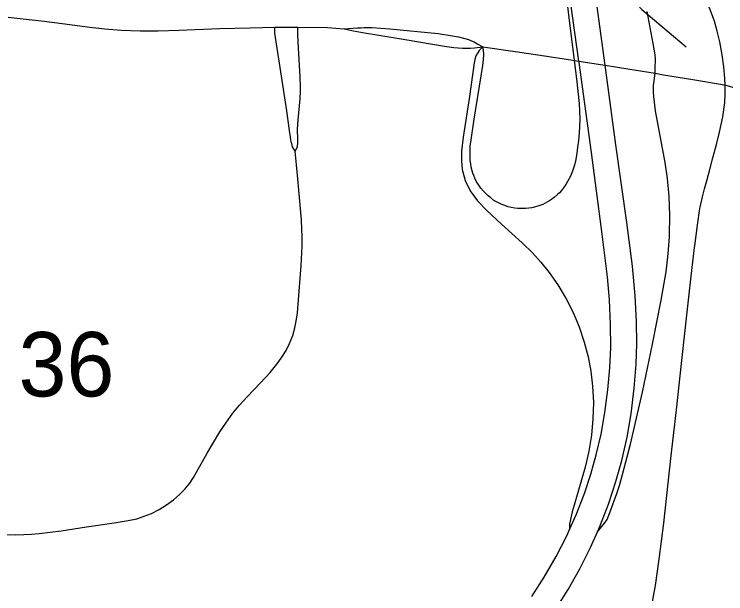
# Model space of a CAD drawing. Extents: x 0 to 34, y 0 to 22.
# Drawn here: x 24.2695 to 24.7319, y 15.2254 to 15.6018 of the extents above; entities that cross this region are included whole.
import ezdxf

# ---------------------------------------------------------------- set-up
doc = ezdxf.new("R2010")
doc.units = 0
for name, color, linetype in [('GM_X_City_Street', 7, 'Continuous'), ('GM_X_County_Road', 7, 'Continuous'), ('GM_X_Interchange_Ramps', 7, 'Continuous'), ('GM_X_Minor_River', 7, 'Continuous'), ('GM_X_Section_Text', 7, 'Continuous'), ('GM_X_State_Route', 7, 'Continuous'), ('GM_X_Township_Road', 7, 'Continuous')]:
    doc.layers.add(name, color=color, linetype=linetype)

msp = doc.modelspace()

# ---------------------------------------------------------------- linework, layer by layer
at = {"layer": 'GM_X_City_Street'}
msp.add_line((24.48399, 15.59231), (24.48502, 15.59207), dxfattribs=at)
for points in [[(24.26558, 15.59991), (24.28906, 15.59739), (24.30078, 15.59585), (24.31862, 15.59332), (24.32847, 15.59223), (24.33897, 15.59149), (24.35136, 15.591), (24.36313, 15.59096), (24.37676, 15.59139), (24.40285, 15.59256), (24.42276, 15.59298), (24.43881, 15.59337), (24.45375, 15.59335), (24.47322, 15.5932), (24.48399, 15.59231)], [(24.45214, 15.51274), (24.45106, 15.51453), (24.45047, 15.51575), (24.44984, 15.51772), (24.44961, 15.51864), (24.44929, 15.52032), (24.4482, 15.52785), (24.44665, 15.53915), (24.44197, 15.56998), (24.43928, 15.58662), (24.43893, 15.58951), (24.43879, 15.5911), (24.43881, 15.59337)], [(24.45214, 15.51274), (24.45286, 15.51385), (24.45327, 15.51481), (24.45354, 15.51584), (24.45365, 15.51659), (24.45373, 15.51751), (24.45379, 15.51868), (24.45378, 15.52066), (24.4537, 15.52696), (24.45399, 15.53323), (24.45535, 15.54681), (24.4555, 15.55176), (24.45549, 15.55424), (24.45531, 15.56103), (24.45428, 15.57967), (24.45392, 15.58867), (24.45375, 15.59335)], [(24.48399, 15.59231), (24.49257, 15.59302), (24.49495, 15.59305), (24.49702, 15.59315), (24.50187, 15.59318), (24.51373, 15.59235), (24.54503, 15.5892), (24.55299, 15.58803), (24.5583, 15.587), (24.56471, 15.58528), (24.56664, 15.58461), (24.5684, 15.5838), (24.57091, 15.58238), (24.57415, 15.58053)], [(24.48502, 15.59207), (24.49012, 15.5909), (24.49706, 15.58964), (24.50518, 15.58832), (24.52364, 15.58548), (24.54146, 15.58239), (24.5491, 15.58102), (24.55512, 15.58025), (24.56088, 15.57983), (24.56414, 15.57971), (24.56607, 15.57977), (24.56866, 15.58006), (24.57415, 15.58053)], [(24.57415, 15.58053), (24.5982, 15.57713), (24.6141, 15.5747), (24.63129, 15.57209), (24.6334, 15.57177), (24.63655, 15.57128), (24.65207, 15.56886), (24.65354, 15.56864), (24.66968, 15.56617), (24.68598, 15.56345), (24.69153, 15.56253), (24.7106, 15.55939)], [(24.26461, 15.26383), (24.27024, 15.26365), (24.27585, 15.26378), (24.28084, 15.26402), (24.28581, 15.26444), (24.30001, 15.26627), (24.31659, 15.2688), (24.33441, 15.27136), (24.34366, 15.27286), (24.34917, 15.27414), (24.35397, 15.27566), (24.35865, 15.27753), (24.36372, 15.28009), (24.36854, 15.28306), (24.3731, 15.28643), (24.3769, 15.28975), (24.38041, 15.29338), (24.38361, 15.29729), (24.38608, 15.30095), (24.395, 15.31663), (24.40324, 15.33044), (24.40696, 15.33611), (24.41169, 15.34257), (24.41599, 15.34781), (24.42091, 15.35335), (24.42953, 15.36229), (24.43584, 15.36919), (24.44101, 15.37547), (24.44389, 15.37959), (24.44615, 15.38338), (24.4484, 15.3879), (24.45049, 15.39318), (24.45193, 15.39801), (24.45283, 15.40233), (24.45358, 15.40793), (24.45495, 15.42467), (24.45592, 15.43831), (24.45658, 15.45137), (24.45657, 15.45795), (24.45649, 15.46176), (24.45618, 15.46844), (24.45588, 15.47302), (24.45363, 15.49731), (24.45214, 15.51274)]]:
    msp.add_lwpolyline(points, dxfattribs=at)
at = {"layer": 'GM_X_County_Road'}
for points in [[(24.72966, 15.57549), (24.72811, 15.58377), (24.72646, 15.59087), (24.72458, 15.59729), (24.72168, 15.60533), (24.71787, 15.61436), (24.71311, 15.62574), (24.71086, 15.63191), (24.7086, 15.63779), (24.70674, 15.64386), (24.70469, 15.65101), (24.70253, 15.66042), (24.70167, 15.66422)], [(24.7316, 15.55576), (24.73126, 15.5602), (24.73077, 15.56755), (24.72966, 15.57549)], [(24.71517, 15.47555), (24.71531, 15.47652), (24.71688, 15.48309), (24.71815, 15.48828), (24.71982, 15.49445), (24.72158, 15.50092), (24.72363, 15.50855), (24.72599, 15.51708), (24.72784, 15.52511), (24.7301, 15.5352), (24.73127, 15.54451), (24.73165, 15.54992), (24.7316, 15.55576)], [(24.71165, 15.45031), (24.71178, 15.45135), (24.71364, 15.46487), (24.71517, 15.47555)], [(24.68327, 15.21428), (24.68618, 15.23076), (24.68876, 15.24793), (24.6916, 15.27132), (24.69645, 15.31513), (24.69986, 15.34473), (24.70308, 15.37496), (24.70548, 15.39656), (24.70943, 15.4317), (24.71044, 15.44095), (24.71165, 15.45031)]]:
    msp.add_lwpolyline(points, dxfattribs=at)
at = {"layer": 'GM_X_Interchange_Ramps'}
for points in [[(24.62582, 15.633), (24.6334, 15.57177), (24.63487, 15.55992), (24.63662, 15.54388), (24.63689, 15.53851), (24.63704, 15.53395), (24.63689, 15.52877), (24.63671, 15.52465), (24.63629, 15.51978), (24.63569, 15.51539), (24.63522, 15.51165), (24.63441, 15.50742), (24.63354, 15.5038), (24.6328, 15.50125), (24.63199, 15.49876), (24.63105, 15.49668), (24.62911, 15.49319), (24.6279, 15.49117), (24.62649, 15.4891), (24.62521, 15.48735), (24.62387, 15.48587), (24.62259, 15.4846), (24.62045, 15.48272), (24.61803, 15.48104), (24.61615, 15.47996), (24.61299, 15.47829), (24.61051, 15.47735), (24.60829, 15.47661), (24.60594, 15.47614), (24.60386, 15.4758), (24.60178, 15.4756), (24.59972, 15.47551), (24.59688, 15.47553), (24.59477, 15.47584), (24.59238, 15.47627), (24.59054, 15.47678), (24.58761, 15.47781), (24.58588, 15.47849), (24.58345, 15.47963), (24.58123, 15.48083), (24.57916, 15.48245), (24.57755, 15.48386), (24.57446, 15.48691), (24.57284, 15.48876), (24.57143, 15.49084), (24.56982, 15.49346), (24.56887, 15.49532), (24.56814, 15.49702), (24.56757, 15.49854), (24.56707, 15.50017), (24.56653, 15.50253), (24.56616, 15.50464), (24.56593, 15.50668), (24.56579, 15.50924), (24.56575, 15.51206), (24.5658, 15.51305)], [(24.68598, 15.56345), (24.68611, 15.56848), (24.68618, 15.57063), (24.68618, 15.57278), (24.68606, 15.57551), (24.68481, 15.58278), (24.68097, 15.60355)], [(24.57415, 15.58053), (24.57174, 15.57833), (24.57058, 15.57656), (24.56954, 15.57467), (24.56881, 15.57228), (24.56835, 15.57019), (24.56538, 15.54846), (24.56119, 15.52204), (24.56025, 15.51275), (24.56022, 15.50653), (24.56073, 15.501), (24.56254, 15.49378), (24.56579, 15.48708), (24.57056, 15.48057), (24.5766, 15.47431), (24.58622, 15.46547), (24.59964, 15.45339), (24.60626, 15.44681), (24.61168, 15.44082), (24.61715, 15.43407), (24.62286, 15.42592), (24.62826, 15.41685), (24.63273, 15.40795), (24.63659, 15.39878), (24.64, 15.38878), (24.6425, 15.37915), (24.64422, 15.36998), (24.64538, 15.36011), (24.64589, 15.34954), (24.64561, 15.33898), (24.64464, 15.32845), (24.64297, 15.31801), (24.64064, 15.3077), (24.63338, 15.28291), (24.63223, 15.27864), (24.63125, 15.27472), (24.63046, 15.2705), (24.63046, 15.26713)], [(24.5658, 15.51305), (24.56593, 15.51602), (24.56638, 15.5201), (24.56835, 15.53361), (24.57302, 15.56177), (24.57407, 15.56843), (24.57456, 15.57247), (24.57461, 15.57564), (24.57443, 15.57852), (24.57415, 15.58053)], [(24.69546, 15.45828), (24.6957, 15.47096), (24.69523, 15.48336), (24.69408, 15.4951), (24.69251, 15.50554), (24.68634, 15.53914), (24.68514, 15.54838), (24.68501, 15.55124), (24.68495, 15.55273), (24.68507, 15.55548), (24.68536, 15.55844), (24.68598, 15.56345)], [(24.64858, 15.2656), (24.65322, 15.27118), (24.65478, 15.27364), (24.65714, 15.27913), (24.66116, 15.29051), (24.66283, 15.2957), (24.66489, 15.30287), (24.67006, 15.32245), (24.67781, 15.3564), (24.68439, 15.38742), (24.69002, 15.41608), (24.69311, 15.43445), (24.6946, 15.44616), (24.69544, 15.4573), (24.69546, 15.45828)]]:
    msp.add_lwpolyline(points, dxfattribs=at)
at = {"layer": 'GM_X_Minor_River'}
msp.add_lwpolyline([(24.38207, 15.87893), (24.41407, 15.84789), (24.42501, 15.82602), (24.42745, 15.81534), (24.42493, 15.80286), (24.42976, 15.77922), (24.45363, 15.7586), (24.48511, 15.73935), (24.52995, 15.70577), (24.62443, 15.65029), (24.65809, 15.62606), (24.67739, 15.60478), (24.70611, 15.58065)], dxfattribs=at)
at = {"layer": 'GM_X_State_Route'}
for points in [[(24.62128, 15.21507), (24.62956, 15.22816), (24.63719, 15.24164), (24.64412, 15.25549), (24.64858, 15.2656), (24.65012, 15.26909), (24.65569, 15.28354), (24.66055, 15.29825), (24.66435, 15.31198), (24.66776, 15.32708), (24.67042, 15.34234), (24.67251, 15.35895), (24.67373, 15.37439), (24.67417, 15.388), (24.674, 15.40225), (24.67308, 15.41896), (24.67126, 15.4381), (24.66761, 15.46642), (24.66056, 15.51689), (24.65354, 15.56864), (24.64945, 15.59878), (24.6447, 15.63324)], [(24.60586, 15.22361), (24.61396, 15.23618), (24.62177, 15.24965), (24.62861, 15.26296), (24.63046, 15.26713), (24.63468, 15.27663), (24.64009, 15.29058), (24.64423, 15.30299), (24.64779, 15.31559), (24.65087, 15.32895), (24.6534, 15.34306), (24.65539, 15.35788), (24.65664, 15.37216), (24.65719, 15.38524), (24.65714, 15.40019), (24.65635, 15.41637), (24.65505, 15.43125), (24.65166, 15.45902), (24.64459, 15.512), (24.63666, 15.57048), (24.63655, 15.57128), (24.6312, 15.60862)]]:
    msp.add_lwpolyline(points, dxfattribs=at)
at = {"layer": 'GM_X_Township_Road'}
for points in [[(24.7106, 15.55939), (24.72845, 15.55631), (24.7316, 15.55576)], [(24.77987, 15.51494), (24.77184, 15.52065), (24.76748, 15.52405), (24.76481, 15.52654), (24.76355, 15.52786), (24.76144, 15.53006), (24.75793, 15.53432), (24.75233, 15.54179), (24.74956, 15.5452), (24.74784, 15.54705), (24.74647, 15.54836), (24.7445, 15.54997), (24.74134, 15.55211), (24.7371, 15.55404), (24.7316, 15.55576)]]:
    msp.add_lwpolyline(points, dxfattribs=at)

# ---------------------------------------------------------------- texts
at = {"layer": 'GM_X_Section_Text'}
msp.add_text('36', height=0.041856, rotation=0, dxfattribs=at).set_placement((24.27233, 15.35353))

doc.saveas('drawing.dxf')
